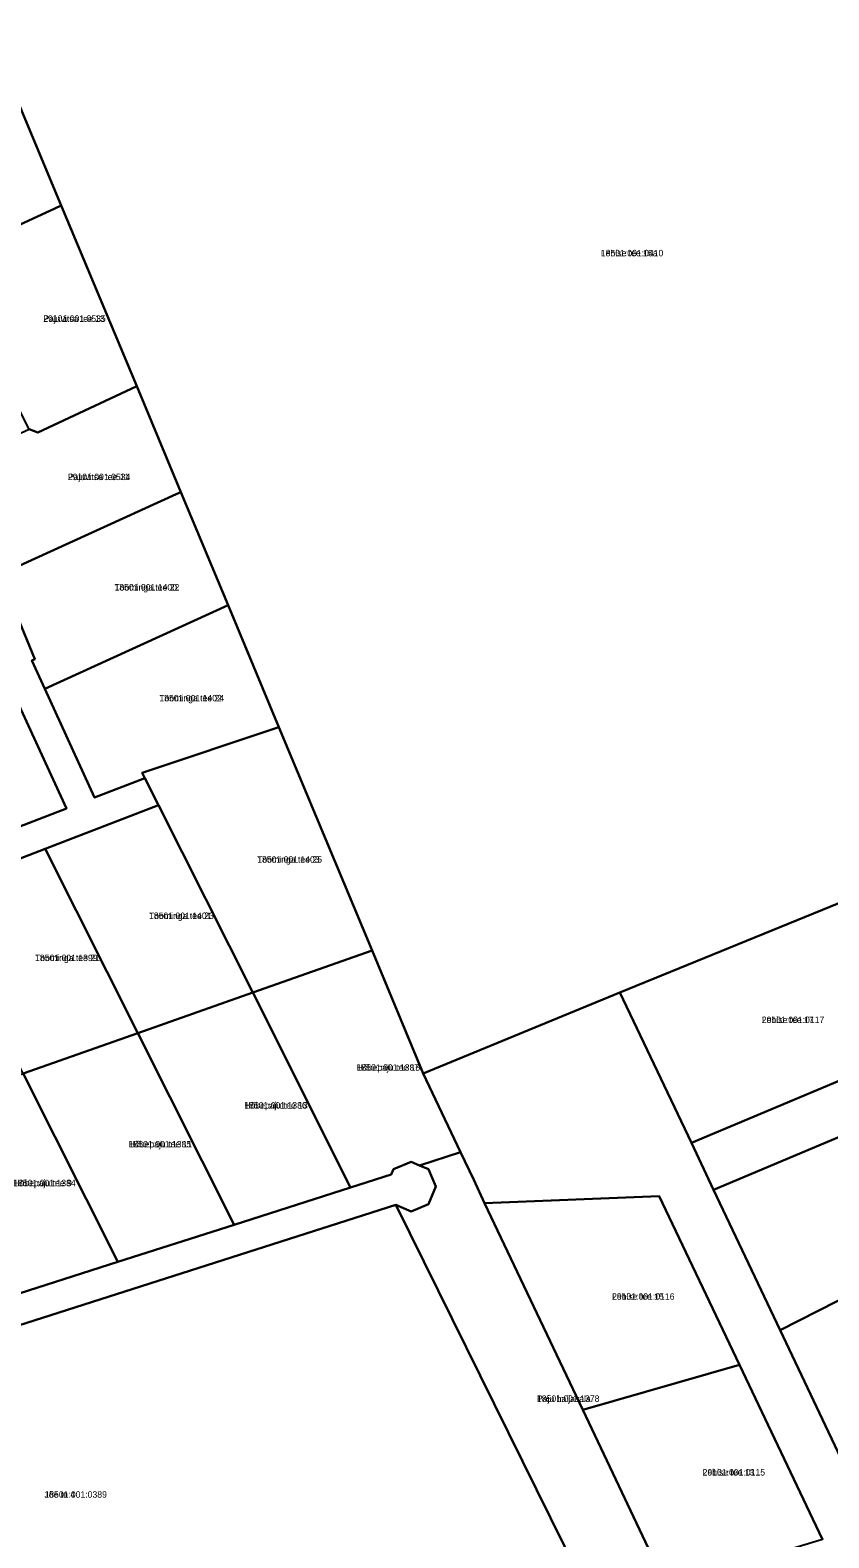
# Model space of a CAD drawing. Extents: x 660838 to 697091, y 6455678 to 6479886.
# Drawn here: x 664124 to 664309.4, y 6468601.6 to 6468951.8 of the extents above; entities that cross this region are included whole.
import ezdxf

# ---------------------------------------------------------------- set-up
doc = ezdxf.new("R2010")
doc.units = 0
for name, color, linetype in [('L_AADRESS', 7, 'Continuous'), ('PIIR', 7, 'Continuous'), ('TUNNUS', 7, 'Continuous')]:
    doc.layers.add(name, color=color, linetype=linetype)

msp = doc.modelspace()

# ---------------------------------------------------------------- linework, layer by layer
at = {"layer": 'PIIR'}
for points in [[(664260.89, 6468728.24), (664215.23, 6468709.47), (664203.34, 6468738), (664181.69, 6468789.93), (664169.9, 6468818.21), (664158.93, 6468844.48), (664148.69, 6468869.1), (664131.18, 6468911.08), (664118.18, 6468942.3), (664094.63, 6468998.74), (664093.92, 6469001.04), (664103.77, 6469005.34), (664107.11, 6469006.8), (664141.06, 6469021.65), (664266.53, 6469076.5), (664295.47, 6469089.15), (664296.36, 6469086.56), (664300.85, 6469048.07), (664302.86, 6469044.36), (664310.57, 6469047.99), (664311.87, 6469044.98), (664419.02, 6468792.9), (664365.27, 6468770.92), (664311.75, 6468749.04)], [(664116.19, 6468941.37), (664118.18, 6468942.3), (664131.18, 6468911.08), (664129.72, 6468910.38), (664105.31, 6468899.11), (664104.57, 6468900.91), (664100.52, 6468902.61), (664096.45, 6468900.93), (664095.57, 6468898.92), (664082.04, 6468925.58)], [(664129.72, 6468910.38), (664131.18, 6468911.08), (664148.69, 6468869.1), (664147.4, 6468868.47), (664125.7, 6468858.36), (664123.7, 6468859.08), (664105.59, 6468894.95), (664106.26, 6468896.86), (664105.31, 6468899.11)], [(664147.4, 6468868.47), (664148.69, 6468869.1), (664158.93, 6468844.48), (664157.82, 6468844), (664117.12, 6468825.46), (664106.02, 6468850.99), (664123.7, 6468859.08), (664125.7, 6468858.36)], [(664125.07, 6468805.66), (664120.77, 6468816.05), (664117.12, 6468825.46), (664157.82, 6468844), (664158.93, 6468844.48), (664169.9, 6468818.21), (664127.36, 6468798.79), (664124.35, 6468805.36)], [(664138.92, 6468773.57), (664127.36, 6468798.79), (664169.9, 6468818.21), (664181.69, 6468789.93), (664149.99, 6468779.3), (664150.6, 6468778.08)], [(663967.19, 6468699.73), (663964.06, 6468706.03), (663998.36, 6468719.27), (664032.21, 6468732.35), (664066.87, 6468745.74), (664100.46, 6468758.71), (664132.37, 6468771.04), (664117.86, 6468802.66), (664114.73, 6468801.36), (664112, 6468808), (664110.56, 6468811.83), (664120.77, 6468816.05), (664125.07, 6468805.66), (664124.35, 6468805.36), (664127.36, 6468798.79), (664138.92, 6468773.57), (664150.6, 6468778.08), (664153.76, 6468771.79), (664127.47, 6468761.64), (664101.23, 6468751.5), (664074.98, 6468741.37), (664048.74, 6468731.23), (664022.5, 6468721.09), (663994.85, 6468710.42)], [(664100.46, 6468758.71), (664081.76, 6468795.18), (664090.17, 6468798.64), (664112, 6468808), (664114.73, 6468801.36), (664117.86, 6468802.66), (664132.37, 6468771.04)], [(664150.6, 6468778.08), (664149.99, 6468779.3), (664181.69, 6468789.93), (664203.34, 6468738), (664175.64, 6468728.23), (664153.76, 6468771.79)], [(664148.97, 6468718.82), (664127.47, 6468761.64), (664153.76, 6468771.79), (664175.64, 6468728.23)], [(664122.36, 6468709.42), (664101.23, 6468751.5), (664127.47, 6468761.64), (664148.97, 6468718.82)], [(664277.48, 6468693.31), (664260.89, 6468728.24), (664311.75, 6468749.04), (664326.48, 6468713.95)], [(664198.37, 6468682.98), (664175.64, 6468728.23), (664203.34, 6468738), (664215.23, 6468709.47), (664223.91, 6468691.15), (664214.39, 6468688.1), (664212.4, 6468688.93), (664208.33, 6468687.24), (664207.81, 6468686)], [(664171.32, 6468674.33), (664148.97, 6468718.82), (664175.64, 6468728.23), (664198.37, 6468682.98)], [(664144.32, 6468665.69), (664122.36, 6468709.42), (664148.97, 6468718.82), (664171.32, 6468674.33)], [(664117.32, 6468657.06), (664095.74, 6468700.03), (664122.36, 6468709.42), (664144.32, 6468665.69)], [(664298.12, 6468649.82), (664282.63, 6468682.45), (664338.86, 6468706.15), (664351.19, 6468676.87)], [(664011.82, 6468610.76), (664006.4, 6468621.58), (664034.89, 6468630.69), (664063.33, 6468639.79), (664090.33, 6468648.43), (664117.32, 6468657.06), (664144.32, 6468665.69), (664171.32, 6468674.33), (664198.37, 6468682.98), (664207.81, 6468686), (664208.33, 6468687.24), (664212.4, 6468688.93), (664214.39, 6468688.1), (664216.46, 6468687.24), (664218.15, 6468683.18), (664216.46, 6468679.11), (664212.4, 6468677.43), (664208.84, 6468678.98), (664029.43, 6468621.6)], [(664257.87, 6468579.74), (664208.84, 6468678.98), (664212.4, 6468677.43), (664216.46, 6468679.11), (664218.15, 6468683.18), (664216.46, 6468687.24), (664214.39, 6468688.1), (664223.91, 6468691.15), (664226.94, 6468684.75), (664229.48, 6468679.37), (664252.28, 6468631.31), (664271.72, 6468590.32), (664274.43, 6468584.62)], [(664252.28, 6468631.31), (664229.48, 6468679.37), (664270.04, 6468680.98), (664288.66, 6468641.77)], [(664156.44, 6468551.21), (664150.84, 6468549.63), (664113.09, 6468547.2), (664079.12, 6468545.02), (664052.46, 6468543.3), (664045.73, 6468542.87), (664045.52, 6468542.86), (664020.16, 6468591.48), (664010.85, 6468610.16), (664011.82, 6468610.76), (664029.43, 6468621.6), (664208.84, 6468678.98), (664257.87, 6468579.74), (664236.44, 6468573.71), (664197.17, 6468562.66)], [(664313.61, 6468617.19), (664298.12, 6468649.82), (664351.19, 6468676.87), (664358.3, 6468660.01), (664367.93, 6468643.89)], [(664271.72, 6468590.32), (664252.28, 6468631.31), (664288.66, 6468641.77), (664307.92, 6468601.21)]]:
    msp.add_lwpolyline(points, close=True, dxfattribs=at)
for points in [[(664307.92, 6468601.21), (664288.66, 6468641.77), (664270.04, 6468680.98), (664229.48, 6468679.37), (664226.94, 6468684.75), (664223.91, 6468691.15), (664215.23, 6468709.47), (664260.89, 6468728.24), (664277.48, 6468693.31), (664282.63, 6468682.45), (664298.12, 6468649.82), (664313.61, 6468617.19), (664329.19, 6468584.39)], [(664338.86, 6468706.15), (664282.63, 6468682.45), (664277.48, 6468693.31), (664326.48, 6468713.95)]]:
    msp.add_lwpolyline(points, dxfattribs=at)

# ---------------------------------------------------------------- texts
at = {"layer": 'L_AADRESS'}
for s, p in [('Lehise tee 15a', (664256.47, 6468899.26)), ('Pajuvitsa tee 13', (664127, 6468884.04)), ('Pajuvitsa tee 11', (664132.7, 6468847.28)), ('Toominga tee 22', (664143.54, 6468821.63)), ('Toominga tee 24', (664153.95, 6468795.89)), ('Toominga tee 25', (664176.67, 6468758.42)), ('Toominga tee 23', (664151.55, 6468745.34)), ('Toominga tee 21', (664125.1, 6468735.56)), ('Lehise tee 17', (664293.85, 6468721.17)), ('Hõbepaju tee 15', (664199.77, 6468710.09)), ('Hõbepaju tee 13', (664173.67, 6468701.31)), ('Hõbepaju tee 11', (664146.84, 6468692.28)), ('Hõbepaju tee 9', (664120.03, 6468683.26)), ('Lehise tee 15', (664259.07, 6468656.9)), ('Paju haljasala', (664241.64, 6468633.17)), ('Lehise tee 13', (664280.1, 6468616.07)), ('Jõe tn 4', (664127.27, 6468610.92))]:
    msp.add_text(s, height=1.5, dxfattribs=at).set_placement(p)
at = {"layer": 'TUNNUS'}
for s, p in [('18501:001:0410', (664256.47, 6468899.26)), ('29101:001:0535', (664127, 6468884.04)), ('29101:001:0534', (664132.7, 6468847.28)), ('18501:001:1400', (664143.54, 6468821.63)), ('18501:001:1402', (664153.95, 6468795.89)), ('18501:001:1403', (664176.67, 6468758.42)), ('18501:001:1401', (664151.55, 6468745.34)), ('18501:001:1399', (664125.1, 6468735.56)), ('29101:001:0117', (664293.85, 6468721.17)), ('18501:001:1387', (664199.77, 6468710.09)), ('18501:001:1386', (664173.67, 6468701.31)), ('18501:001:1385', (664146.84, 6468692.28)), ('18501:001:1384', (664120.03, 6468683.26)), ('29101:001:0116', (664259.07, 6468656.9)), ('18501:001:1378', (664241.64, 6468633.17)), ('29101:001:0115', (664280.1, 6468616.07)), ('18501:001:0389', (664127.27, 6468610.92))]:
    msp.add_text(s, height=1.5, dxfattribs=at).set_placement(p)

doc.saveas('drawing.dxf')
